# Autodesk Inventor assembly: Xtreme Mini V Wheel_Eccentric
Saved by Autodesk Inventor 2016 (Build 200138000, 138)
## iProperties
Created: 2016-01
Part Number: Xtreme Mini V Wheel_Eccentric
Document SubType Name: Assembly
Designer: John
Author: John
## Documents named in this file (6)
- D:\3D Printer Designs\John Ledden Designs\DLP Printer\V2\Xtreme Mini V Wheel_Eccentric.iam
- D:\3D Printer Designs\John Ledden Designs\DLP Printer\V2\Precision Shim 8 x 5 x 1.ipt
- D:\3D Printer Designs\John Ledden Designs\DLP Printer\V2\Xtreme Mini V Wheel.ipt
- D:\3D Printer Designs\John Ledden Designs\DLP Printer\V2\Mini Eccentric Spacer 6mm.ipt
- D:\3D Printer Designs\John Ledden Designs\DLP Printer\V2\Ball Bearing 5 x 10 x 4.2.ipt
- D:\3D Printer Designs\John Ledden Designs\DLP Printer\V2\Nylon Insert Lock Nut M5.ipt
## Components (7 placed, 7 different names)
1. Precision Shim 8 x 5 x 1_1014
2. Xtreme Mini V Wheel_1015
3. Precision Shim 8 x 5 x 1_1016
4. Mini Eccentric Spacer 6mm_1017
5. Ball Bearing 5 x 10 x 4.2_1018
6. Nylon Insert Lock Nut M5_1019
7. Ball Bearing 5 x 10 x 4.2_1020
